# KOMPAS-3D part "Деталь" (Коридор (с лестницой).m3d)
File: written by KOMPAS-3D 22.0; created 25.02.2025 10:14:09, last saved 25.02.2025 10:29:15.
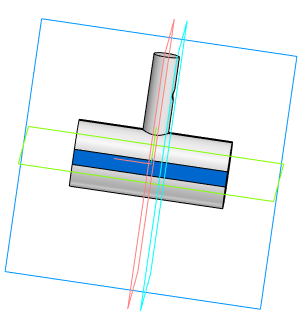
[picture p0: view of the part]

Document properties: Автор: Пользователь Windows; Полное имя файла: C:\Users\Student\Documents\Картошечка\База Сабнатика\Коридор\Коридор (с лестницой).m3d

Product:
- Body: Тело 1
    Масса: 0.028645
- Part/product: Деталь
    Масса: 0.030965

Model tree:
1. Эскиз:1
2. Элемент выдавливания:1
     Расстояние 1 = 30
3. Эскиз:2  (with: Элемент выдавливания:1)
4. Элемент выдавливания:2
     Расстояние 1 = 15; Расстояние 2 = 2
5. Смещенная плоскость:1
     Расстояние = 2.5
6. Эскиз:3  (with: Элемент выдавливания:1, Элемент выдавливания:2)
7. Элемент выдавливания:3
     Расстояние 2 = 0.25

Expressions: 15/2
